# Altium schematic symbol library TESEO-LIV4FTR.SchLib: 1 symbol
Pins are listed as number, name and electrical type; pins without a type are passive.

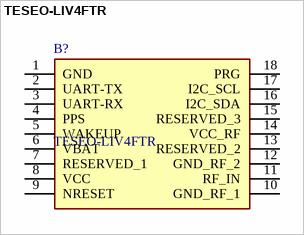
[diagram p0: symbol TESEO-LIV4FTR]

## TESEO-LIV4FTR
designator B?
Tiny dual-band GNSS low power and measurement engine modules; Manufacturer_Name: STMicroelectronics; Geometry.Height: 2.3mm
footprint TESEOLIV4FTR
pins: 1 GND, 2 UART-TX, 3 UART-RX, 4 PPS, 5 WAKEUP, 6 VBAT, 7 RESERVED_1, 8 VCC, 9 NRESET, 10 GND_RF_1, 11 RF_IN, 12 GND_RF_2, 13 RESERVED_2, 14 VCC_RF, 15 RESERVED_3, 16 I2C_SDA, 17 I2C_SCL, 18 PRG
